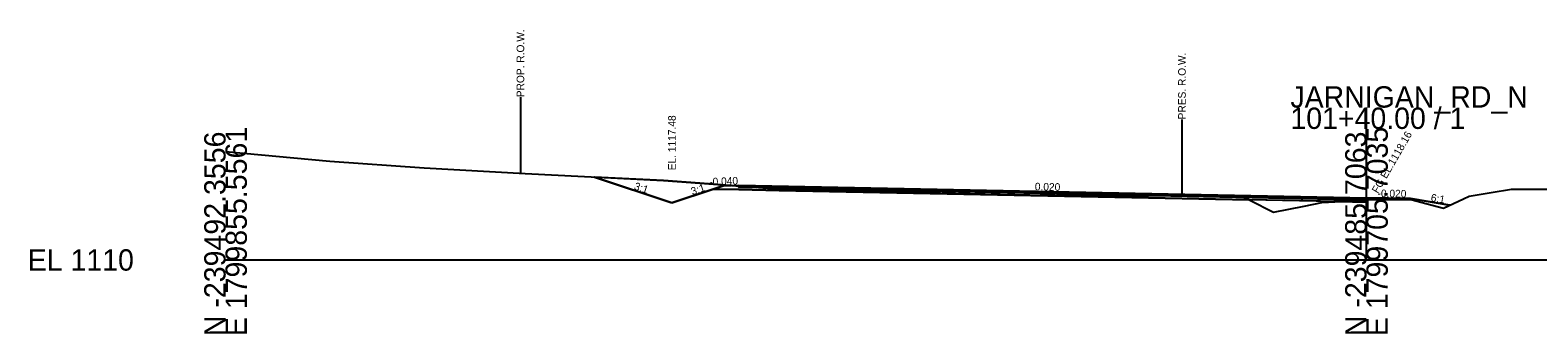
# Model space of a CAD drawing. Extents: x 214513 to 217151, y 214739 to 216780.
# Drawn here: x 215422.7 to 215620.9, y 216738.7 to 216778.5 of the extents above; entities that cross this region are included whole.
import ezdxf

# ---------------------------------------------------------------- set-up
doc = ezdxf.new("R2010")
doc.units = 0
for name, color, linetype in [('CONCEPT - TRANSPORTATION - Roads Text', 7, 'Continuous'), ('DESIGN - CENTERLINE - Proposed', 7, 'Continuous'), ('DESIGN - CENTERLINE - Proposed Text', 7, 'Continuous'), ('DESIGN - DRAINAGE - Special Ditches', 7, 'Continuous'), ('DESIGN - EARTHWORK - Shapes', 7, 'Continuous'), ('DESIGN - ROW - Right-of-Way Linework', 7, 'Continuous'), ('DESIGN - TRANSPORTATION - Text', 7, 'Continuous'), ('DESIGN - TYPICAL - Slope Tie Text', 7, 'Continuous'), ('Section', 7, 'Continuous'), ('SURVEY - DTM GRAPHICS - Triangles', 7, 'Continuous'), ('SURVEY - PROPERTY - ROW Lines', 7, 'Continuous'), ('XSCell', 7, 'Continuous')]:
    doc.layers.add(name, color=color, linetype=linetype)

msp = doc.modelspace()

# ---------------------------------------------------------------- linework, layer by layer
at = {"layer": 'DESIGN - DRAINAGE - Special Ditches'}
for points in [[(215507.05, 216755.85), (215496.87, 216759.24)], [(215513.78, 216758.09), (215507.05, 216755.85)], [(215515.86, 216758.17), (215515.86, 216757.92), (215521.15, 216757.82), (215598.36, 216756.27), (215598.36, 216755.94), (215521.15, 216757.49), (215515.86, 216757.59), (215512.49, 216757.66), (215513.78, 216758.09), (215515.86, 216758.17)], [(215515.86, 216758.17), (215598.36, 216756.52), (215598.36, 216756.42), (215515.86, 216758.07), (215515.86, 216758.07), (215515.86, 216758.17), (215515.86, 216758.17)], [(215515.86, 216758.07), (215598.36, 216756.42), (215598.36, 216756.27), (215598.36, 216756.27), (215515.86, 216757.92), (215515.86, 216757.92), (215515.86, 216757.92), (215515.86, 216758.07), (215515.86, 216758.07)], [(215598.36, 216756.52), (215598.36, 216756.52), (215598.36, 216756.42), (215598.36, 216756.42), (215604.16, 216756.31), (215604.16, 216756.41), (215598.36, 216756.52)], [(215604.16, 216756.41), (215609.32, 216755.55)]]:
    msp.add_lwpolyline(points, dxfattribs=at)
at = {"layer": 'DESIGN - EARTHWORK - Shapes'}
for p, q in [((215496.87, 216759.24), (215507.05, 216755.85)), ((215513.78, 216758.09), (215514.72, 216758.13)), ((215514.72, 216758.13), (215513.78, 216758.09)), ((215515.86, 216758.05), (215514.72, 216758.13)), ((215518.23, 216757.88), (215515.86, 216758.05)), ((215515.86, 216758.05), (215515.86, 216757.92)), ((215515.86, 216757.92), (215518.23, 216757.88)), ((215582.2, 216756.6), (215571.8, 216756.81)), ((215571.8, 216756.81), (215582.2, 216756.6)), ((215581.87, 216756.75), (215579.68, 216756.8)), ((215579.68, 216756.8), (215581.87, 216756.75)), ((215582.2, 216756.6), (215581.87, 216756.75)), ((215582.93, 216756.25), (215582.2, 216756.6)), ((215594.68, 216756.02), (215582.93, 216756.25)), ((215594.68, 216756.02), (215598.36, 216755.94)), ((215604.16, 216756.31), (215598.36, 216756.42)), ((215598.36, 216756.42), (215598.36, 216756.27)), ((215598.36, 216756.27), (215598.36, 216756.22)), ((215598.36, 216756.22), (215598.62, 216756.24)), ((215598.36, 216755.94), (215598.36, 216756.22)), ((215604.16, 216756.41), (215604.16, 216756.31)), ((215609.32, 216755.55), (215604.16, 216756.41))]:
    msp.add_line(p, q, dxfattribs=at)
for points in [[(215514.72, 216758.13), (215510.72, 216758.42), (215505.95, 216758.79), (215496.87, 216759.24)], [(215507.05, 216755.85), (215512.49, 216757.66), (215513.78, 216758.09)], [(215513.78, 216758.09), (215512.49, 216757.66), (215515.86, 216757.59), (215521.15, 216757.49), (215582.93, 216756.25)], [(215518.23, 216757.88), (215515.86, 216757.92), (215515.86, 216758.05)], [(215571.8, 216756.81), (215560.76, 216756.78), (215554.12, 216756.87), (215522.8, 216757.56), (215521.35, 216757.65), (215518.23, 216757.88)], [(215579.68, 216756.8), (215578.02, 216756.82), (215571.8, 216756.81)], [(215581.87, 216756.75), (215581.85, 216756.77), (215579.68, 216756.8)], [(215582.93, 216756.25), (215583.03, 216756.21), (215586.15, 216754.62), (215590.15, 216755.41), (215592.48, 216755.91), (215594.68, 216756.02)], [(215598.36, 216756.22), (215595.08, 216756.04), (215594.68, 216756.02)], [(215598.62, 216756.24), (215604.09, 216756.31), (215604.16, 216756.31)], [(215604.16, 216756.31), (215604.21, 216756.29), (215608.48, 216755.16), (215609.32, 216755.55)]]:
    msp.add_lwpolyline(points, dxfattribs=at)
at = {"layer": 'DESIGN - ROW - Right-of-Way Linework'}
msp.add_lwpolyline([(215487.13, 216769.72), (215487.13, 216759.72)], dxfattribs=at)
at = {"layer": 'SURVEY - DTM GRAPHICS - Triangles'}
msp.add_lwpolyline([(215448.36, 216762.61), (215462.06, 216761.31), (215474.46, 216760.47), (215487.77, 216759.69), (215505.95, 216758.79), (215510.72, 216758.42), (215521.35, 216757.65), (215522.8, 216757.56), (215554.12, 216756.87), (215560.76, 216756.78), (215578.02, 216756.82), (215581.85, 216756.77), (215583.03, 216756.21), (215586.15, 216754.62), (215590.15, 216755.41), (215592.48, 216755.91), (215595.08, 216756.04), (215598.62, 216756.24), (215604.09, 216756.31), (215604.16, 216756.31), (215604.21, 216756.29), (215608.48, 216755.16), (215611.1, 216756.39), (215611.86, 216756.73), (215614.74, 216757.21), (215617.41, 216757.67), (215622.39, 216757.65)], dxfattribs=at)
at = {"layer": 'SURVEY - PROPERTY - ROW Lines'}
msp.add_lwpolyline([(215574.1, 216766.81), (215574.1, 216756.81)], dxfattribs=at)
at = {"layer": 'XSCell'}
for p, q in [((215598.36, 216748.36), (215598.36, 216768.36)), ((215448.36, 216748.36), (215598.36, 216748.36)), ((215598.36, 216748.36), (215748.36, 216748.36))]:
    msp.add_line(p, q, dxfattribs=at)

# ---------------------------------------------------------------- texts
at = {"layer": 'CONCEPT - TRANSPORTATION - Roads Text'}
for s, rotation, p in [('-0.040', 2.2906, (215511.97, 216758.12)), ('0.020', 358.8542, (215554.75, 216757.5)), ('-0.020', 358.8542, (215599.81, 216756.62))]:
    msp.add_text(s, height=1, rotation=rotation, dxfattribs=at).set_placement(p)
at = {"layer": 'DESIGN - CENTERLINE - Proposed'}
msp.add_text('EL. 1117.48', height=1, rotation=90, dxfattribs=at).set_placement((215507.55, 216760.13))
at = {"layer": 'DESIGN - CENTERLINE - Proposed Text'}
msp.add_text('FG EL.1118.16', height=1, rotation=60, dxfattribs=at).set_placement((215599.86, 216757.02))
at = {"layer": 'DESIGN - TRANSPORTATION - Text'}
for s, p in [('PROP. R.O.W.', (215487.63, 216769.72)), ('PRES. R.O.W.', (215574.6, 216766.81))]:
    msp.add_text(s, height=1, rotation=90, dxfattribs=at).set_placement(p)
at = {"layer": 'DESIGN - TYPICAL - Slope Tie Text'}
for s, rotation, p in [('3:1', 341.5651, (215501.99, 216757.64)), ('3:1', 18.4349, (215509.74, 216756.85)), ('6:1', 350.5377, (215606.76, 216756.08))]:
    msp.add_text(s, height=1, rotation=rotation, dxfattribs=at).set_placement(p)
at = {"layer": 'Section'}
msp.add_text('-', height=0.0001, dxfattribs=at).set_placement((215448.36, 216748.36))
at = {"layer": 'XSCell'}
for s, p in [('JARNIGAN_RD_N', (215588.36, 216768.36)), ('101+40.00 / 1', (215588.36, 216765.56)), ('EL 1110', (215422.36, 216746.96))]:
    msp.add_text(s, height=2.8, dxfattribs=at).set_placement(p)
for s, p in [('N -239492.3556', (215448.36, 216738.36)), ('E 1799855.5561', (215451.16, 216738.36)), ('N -239485.7063', (215598.36, 216738.36)), ('E 1799705.7035', (215601.16, 216738.36))]:
    msp.add_text(s, height=2.8, rotation=90, dxfattribs=at).set_placement(p)

doc.saveas('drawing.dxf')
